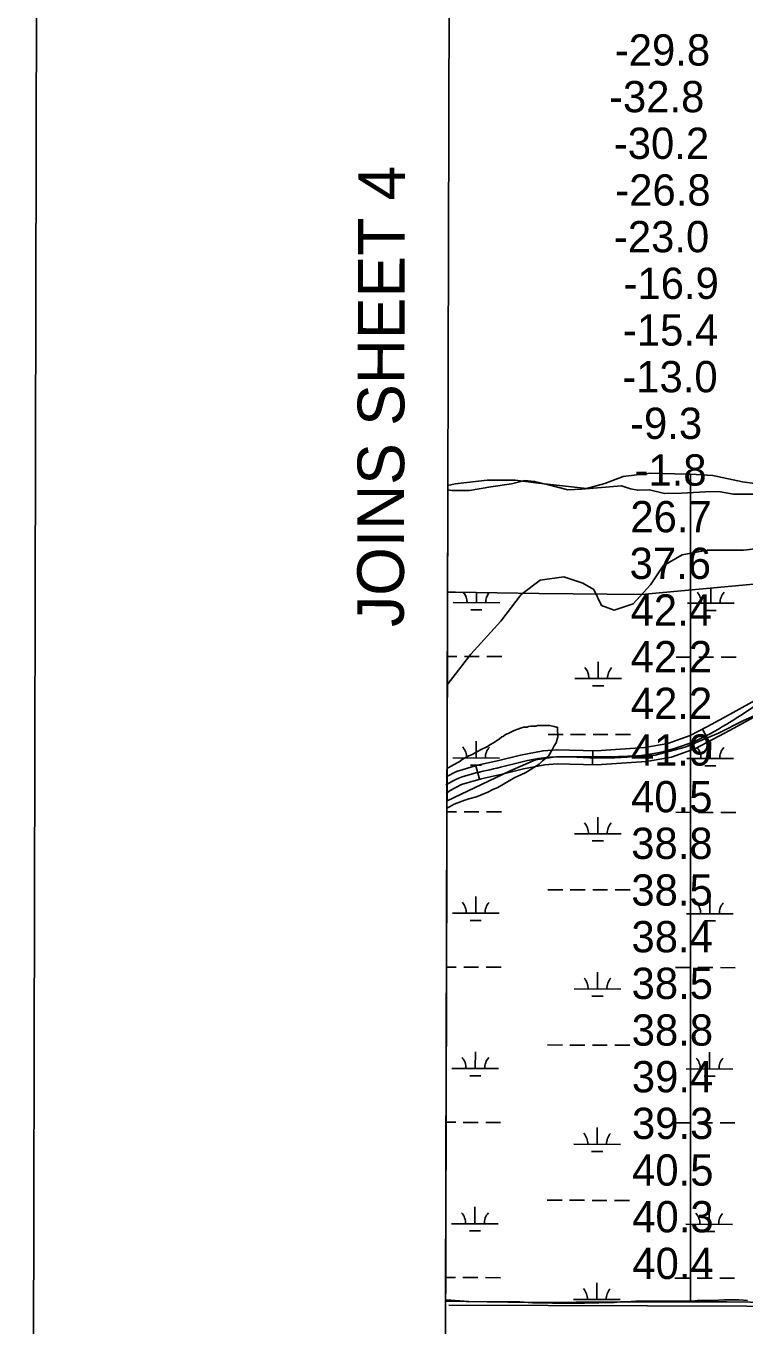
# Model space of a CAD drawing. Extents: x 3180038 to 3217926, y 922069 to 947485.
# Drawn here: x 3183373 to 3184913, y 930412 to 933197 of the extents above; entities that cross this region are included whole.
import ezdxf

# ---------------------------------------------------------------- set-up
doc = ezdxf.new("R2010")
doc.units = 0
for name, color, linetype in [('V-ANNO-SYMB', 7, 'Continuous'), ('V-ANNO-TEXT', 7, 'Continuous'), ('V-GRID-FRAM', 7, 'Continuous'), ('V-RIVR-EDGE', 7, 'Continuous'), ('V-RIVR-RANG', 7, 'Continuous'), ('V-ROAD-CNTR', 7, 'Continuous'), ('V-SITE-VEGE', 7, 'Continuous'), ('V-TOPO-SHOR', 7, 'Continuous'), ('V-WETL-SWMP', 7, 'Continuous')]:
    doc.layers.add(name, color=color, linetype=linetype)

msp = doc.modelspace()

# ---------------------------------------------------------------- linework, layer by layer
at = {"layer": 'V-ANNO-SYMB'}
msp.add_lwpolyline([(3183372.7, 923354.1), (3216455.8, 923279.5), (3216507.5, 946196), (3183424.3, 946270.6), (3183372.7, 923354.1)], dxfattribs=at)
at = {"layer": 'V-GRID-FRAM'}
msp.add_lwpolyline([(3184312.7, 945707.9), (3215616.6, 945637.4), (3215583.5, 927448.1), (3184263.7, 927518.7), (3184312.7, 945707.9)], dxfattribs=at)
at = {"layer": 'V-RIVR-EDGE'}
msp.add_lwpolyline([(3184276.3, 932203.3), (3184285.1, 932201.9), (3184322.5, 932202.1), (3184368.2, 932209.6), (3184412.4, 932216.2), (3184441.6, 932223.2), (3184462, 932221.6), (3184492.2, 932213.9), (3184533.6, 932203.7), (3184562.5, 932205.2), (3184605.8, 932208.7), (3184648.4, 932211.7), (3184667.3, 932205.6), (3184683.1, 932202.5), (3184708.4, 932203.6), (3184740.3, 932195.3), (3184777.2, 932196.4), (3184828.1, 932199.4), (3184856.1, 932199.9), (3184888.4, 932194), (3184938.6, 932194.2)], dxfattribs=at)
at = {"layer": 'V-ROAD-CNTR'}
for p, q in [((3184822, 931690.9), (3184835.8, 931664.2)), ((3184586.9, 931644.2), (3184586.2, 931614.2)), ((3184336, 931612), (3184344.4, 931583.2))]:
    msp.add_line(p, q, dxfattribs=at)
for points in [[(3184272.6, 931588.5), (3184294.6, 931599.9), (3184340.2, 931613.3), (3184385.4, 931623.5), (3184432.2, 931635.1), (3184480.5, 931644.2), (3184509.9, 931646), (3184593.9, 931644.1), (3184698, 931651.1), (3184747.7, 931659.9), (3184795.1, 931676.9), (3184830.8, 931695.4), (3184866.8, 931714.7), (3184961.2, 931766.7)], [(3184272.5, 931553), (3184281.1, 931559.2), (3184305.8, 931571.9), (3184347.7, 931584.2), (3184392.4, 931594.3), (3184438.6, 931605.8), (3184484.2, 931614.4), (3184510.5, 931616), (3184594.6, 931614), (3184701.6, 931621.3), (3184755.4, 931630.8), (3184807.1, 931649.4), (3184844.8, 931668.9), (3184881.1, 931688.3), (3184974.8, 931740)]]:
    msp.add_lwpolyline(points, dxfattribs=at)
msp.add_spline([(3184272.5, 931571.5), (3184273.3, 931572), (3184388.9, 931608.9), (3184482.3, 931629.3), (3184594.3, 931629), (3184801.1, 931663.1), (3184874, 931701.5), (3185066.2, 931799.5), (3185255.8, 931784.9), (3185463.4, 931779.9), (3185599.9, 931763.6), (3185790.3, 931711.5), (3185913, 931645.5), (3186095, 931571.4), (3186297.6, 931563.8), (3186567.5, 931553), (3186727.4, 931556.9), (3186879, 931529.3), (3186914.3, 931400.2), (3186887.7, 931205.9), (3186857.5, 930948.7), (3186884.4, 930867.9), (3186934.5, 930827.1), (3186969.1, 930750.7), (3186952, 930670.5)], degree=3, dxfattribs=at)
at = {"layer": 'V-SITE-VEGE'}
for p, q in [((3184291.7, 932216.1), (3184276.3, 932213)), ((3184360.3, 932223.9), (3184291.7, 932216.1)), ((3184420.8, 932224.4), (3184360.3, 932223.9)), ((3184470.3, 932217.7), (3184420.8, 932224.4)), ((3184573.1, 932206.2), (3184470.3, 932217.7)), ((3184612.9, 932217.3), (3184573.1, 932206.2)), ((3184651.8, 932231.9), (3184612.9, 932217.3)), ((3184710.3, 932239.1), (3184651.8, 932231.9)), ((3184789.3, 932237.1), (3184710.3, 932239.1)), ((3184796.1, 932236.7), (3184789.3, 932237.1)), ((3184844.3, 932234.3), (3184796.1, 932236.7)), ((3184796.1, 932236.7), (3184796.1, 930464.8)), ((3184796.1, 930464.8), (3184796.1, 932236.7)), ((3184907.8, 932220.9), (3184844.3, 932234.3)), ((3184988.1, 932209.2), (3184907.8, 932220.9)), ((3184276.3, 932213), (3184274.7, 931606.3)), ((3184405.4, 931681.1), (3184418.2, 931687.5)), ((3184418.2, 931687.5), (3184426.2, 931690.7)), ((3184426.2, 931690.7), (3184431.8, 931693.1)), ((3184431.8, 931693.1), (3184438.2, 931694.7)), ((3184438.2, 931694.7), (3184446.2, 931694.7)), ((3184446.2, 931694.7), (3184449.4, 931696.3)), ((3184449.4, 931696.3), (3184454.2, 931697.1)), ((3184454.2, 931697.1), (3184464.7, 931697.1)), ((3184464.7, 931697.1), (3184468.7, 931698.7)), ((3184468.7, 931698.7), (3184495.1, 931698.8)), ((3184495.1, 931698.8), (3184503.9, 931696.4)), ((3184503.9, 931696.4), (3184508.7, 931694.8)), ((3184508.7, 931694.8), (3184511.1, 931694.8)), ((3184511.1, 931694.8), (3184511.1, 931686)), ((3184511.1, 931686), (3184511.9, 931679.6)), ((3184359.8, 931653), (3184367.8, 931657.8)), ((3184367.8, 931657.8), (3184377.4, 931663.4)), ((3184377.4, 931663.4), (3184381.4, 931666.6)), ((3184381.4, 931666.6), (3184386.2, 931669.1)), ((3184386.2, 931669.1), (3184391.8, 931673.9)), ((3184391.8, 931673.9), (3184395, 931674.7)), ((3184395, 931674.7), (3184399.8, 931679.5)), ((3184399.8, 931679.5), (3184405.4, 931681.1)), ((3184508.7, 931661.1), (3184503.9, 931654.7)), ((3184511.9, 931673.9), (3184508.7, 931661.1)), ((3184511.9, 931679.6), (3184511.9, 931673.9)), ((3184306.9, 931625.7), (3184319.7, 931633)), ((3184319.7, 931633), (3184328.5, 931636.2)), ((3184328.5, 931636.2), (3184339.7, 931642.6)), ((3184339.7, 931642.6), (3184347.8, 931647.4)), ((3184347.8, 931647.4), (3184359.8, 931653)), ((3184491.9, 931633.1), (3184485.5, 931627.5)), ((3184500.7, 931647.5), (3184491.9, 931633.1)), ((3184503.9, 931654.7), (3184500.7, 931647.5)), ((3184274.7, 931606.3), (3184277.3, 931608.1)), ((3184277.3, 931608.1), (3184288.5, 931614.5)), ((3184288.5, 931614.5), (3184300.5, 931620.9)), ((3184300.5, 931620.9), (3184306.9, 931625.7)), ((3184452.7, 931603.4), (3184443.1, 931597.8)), ((3184466.3, 931612.2), (3184452.7, 931603.4)), ((3184471.9, 931615.4), (3184466.3, 931612.2)), ((3184479.1, 931622.7), (3184471.9, 931615.4)), ((3184485.5, 931627.5), (3184479.1, 931622.7)), ((3184419.9, 931587.4), (3184383.1, 931565.7)), ((3184432.7, 931593), (3184419.9, 931587.4)), ((3184443.1, 931597.8), (3184432.7, 931593)), ((3184362.2, 931555.3), (3184337.4, 931545.7)), ((3184372.6, 931561.7), (3184362.2, 931555.3)), ((3184383.1, 931565.7), (3184372.6, 931561.7)), ((3184274.5, 931521.6), (3184271.6, 930467.4)), ((3184279.8, 931524), (3184274.5, 931521.6)), ((3184290.2, 931529.6), (3184279.8, 931524)), ((3184312.6, 931538.4), (3184290.2, 931529.6)), ((3184321.4, 931541.7), (3184312.6, 931538.4)), ((3184337.4, 931545.7), (3184321.4, 931541.7)), ((3184271.6, 930467.4), (3184282.9, 930466.8)), ((3184282.9, 930466.8), (3184321.4, 930464.4)), ((3184321.4, 930464.4), (3184372.6, 930463.6)), ((3184372.6, 930463.6), (3184430.3, 930463.7)), ((3184430.3, 930463.7), (3184457.5, 930461.3)), ((3184457.5, 930461.3), (3184475.9, 930461.3)), ((3184475.9, 930461.3), (3184500.8, 930460.5)), ((3184500.8, 930460.5), (3184568.9, 930460.6)), ((3184568.9, 930460.6), (3184580.9, 930461.4)), ((3184580.9, 930461.4), (3184600.1, 930461.4)), ((3184600.1, 930461.4), (3184612.9, 930462.2)), ((3184612.9, 930462.2), (3184632.9, 930462.2)), ((3184632.9, 930462.2), (3184646.5, 930463.8)), ((3184646.5, 930463.8), (3184659.4, 930463.9)), ((3184659.4, 930463.9), (3184679.4, 930464.7)), ((3184679.4, 930464.7), (3184796.1, 930464.8)), ((3184796.1, 930464.8), (3184801.1, 930464.8)), ((3184801.1, 930464.8), (3184810.7, 930466.4)), ((3184810.7, 930466.4), (3184843.6, 930466.4)), ((3184843.6, 930466.4), (3184868.4, 930468)), ((3184868.4, 930468), (3184900.4, 930468)), ((3184900.4, 930468), (3184918.1, 930466.4))]:
    msp.add_line(p, q, dxfattribs=at)
at = {"layer": 'V-TOPO-SHOR'}
for points in [[(3184274.6, 931785.9), (3184325.4, 931851.2), (3184389.6, 931922.1), (3184433.5, 931979.5), (3184474.1, 932009.9), (3184524.7, 932016.7), (3184565.3, 932003.2), (3184588.9, 931989.7), (3184605.8, 931955.9), (3184632.8, 931945.8), (3184673.4, 931959.3), (3184710.5, 931999.8), (3184737.6, 932040.3), (3184778.1, 932064), (3184832.1, 932074.1), (3184909.8, 932074.1), (3184997.7, 932084.3)], [(3184273.4, 931536.5), (3184409.9, 931601.2), (3184463.9, 931624.9), (3184507.9, 931631.6), (3184551.8, 931631.6), (3184622.7, 931631.6), (3184720.7, 931635), (3184784.9, 931651.9), (3184855.8, 931682.3), (3184909.8, 931709.3), (3184957.1, 931729.6)], [(3184278.2, 930456.1), (3185342.2, 930452.7), (3185592.2, 930452.7), (3186190.1, 930439.2), (3186217.1, 930459.5), (3186240.7, 930496.6), (3186277.9, 930533.8), (3186335.3, 930567.6), (3186382.6, 930601.3), (3186440, 930648.6), (3186477.2, 930672.3)]]:
    msp.add_lwpolyline(points, dxfattribs=at)
at = {"layer": 'V-WETL-SWMP'}
for p, q in [((3184691, 931979.1), (3184961.8, 932004)), ((3184839.4, 931960.4), (3184839.4, 931992.7)), ((3184271.6, 930465.2), (3184275.7, 931983.9)), ((3184275.7, 931983.9), (3184293.1, 931983.9)), ((3184293.1, 931983.9), (3184471, 931981.1)), ((3184337.5, 931961.5), (3184337.5, 931983.2)), ((3184471, 931981.1), (3184691, 931979.1)), ((3184287.5, 931961.7), (3184387.5, 931961.4)), ((3184325.4, 931946.1), (3184349.4, 931946.1)), ((3184789.4, 931960.5), (3184889.4, 931960.3)), ((3184827.3, 931945), (3184851.3, 931945)), ((3184275.4, 931846.2), (3184295.8, 931846.2)), ((3184311.8, 931846.2), (3184343.8, 931846.1)), ((3184359.8, 931846.1), (3184391.8, 931846)), ((3184598.5, 931799.1), (3184598.6, 931835.1)), ((3184765.7, 931845.1), (3184797.7, 931845.1)), ((3184813.7, 931845), (3184845.7, 931845)), ((3184861.7, 931844.9), (3184893.7, 931844.9)), ((3184548.5, 931799.2), (3184648.5, 931799)), ((3184586.5, 931783.7), (3184610.5, 931783.6)), ((3184336.7, 931628.9), (3184336.8, 931664.9)), ((3184491.4, 931679.3), (3184523.4, 931679.2)), ((3184539.4, 931679.2), (3184571.4, 931679.1)), ((3184587.4, 931679), (3184619.4, 931679)), ((3184635.4, 931678.9), (3184667.4, 931678.9)), ((3184838.6, 931627.7), (3184838.7, 931663.7)), ((3184286.7, 931629), (3184386.7, 931628.8)), ((3184324.7, 931613.5), (3184348.7, 931613.4)), ((3184788.6, 931627.8), (3184888.6, 931627.6)), ((3184826.6, 931612.3), (3184850.6, 931612.3)), ((3184274.5, 931513.6), (3184295, 931513.5)), ((3184311, 931513.5), (3184343, 931513.4)), ((3184359, 931513.4), (3184391, 931513.3)), ((3184597.8, 931466.4), (3184597.9, 931502.4)), ((3184765, 931512.5), (3184797, 931512.4)), ((3184813, 931512.4), (3184845, 931512.3)), ((3184861, 931512.3), (3184893, 931512.2)), ((3184547.8, 931466.5), (3184647.8, 931466.3)), ((3184585.7, 931451), (3184609.7, 931451)), ((3184336, 931296.2), (3184336, 931332.2)), ((3184490.7, 931346.6), (3184522.7, 931346.5)), ((3184538.7, 931346.5), (3184570.7, 931346.4)), ((3184586.7, 931346.4), (3184618.7, 931346.3)), ((3184634.7, 931346.3), (3184666.7, 931346.2)), ((3184837.9, 931295.1), (3184837.9, 931331.1)), ((3184286, 931296.3), (3184386, 931296.1)), ((3184323.9, 931280.8), (3184347.9, 931280.7)), ((3184787.9, 931295.2), (3184887.9, 931294.9)), ((3184825.8, 931279.7), (3184849.8, 931279.6)), ((3184273.6, 931180.9), (3184294.3, 931180.9)), ((3184310.3, 931180.8), (3184342.3, 931180.7)), ((3184358.3, 931180.7), (3184390.3, 931180.6)), ((3184597, 931133.7), (3184597.1, 931169.7)), ((3184764.2, 931179.8), (3184796.2, 931179.7)), ((3184812.2, 931179.7), (3184844.2, 931179.6)), ((3184860.2, 931179.6), (3184892.2, 931179.5)), ((3184547, 931133.9), (3184647, 931133.6)), ((3184585, 931118.3), (3184609, 931118.3)), ((3184335.2, 930963.5), (3184335.3, 930999.5)), ((3184489.9, 931013.9), (3184521.9, 931013.8)), ((3184537.9, 931013.8), (3184569.9, 931013.7)), ((3184585.9, 931013.7), (3184617.9, 931013.6)), ((3184633.9, 931013.6), (3184665.9, 931013.5)), ((3184837.1, 930962.4), (3184837.2, 930998.4)), ((3184285.2, 930963.6), (3184385.2, 930963.4)), ((3184787.1, 930962.5), (3184887.1, 930962.3)), ((3184323.2, 930948.1), (3184347.2, 930948.1)), ((3184825.1, 930947), (3184849.1, 930946.9)), ((3184272.7, 930848.2), (3184293.5, 930848.2)), ((3184309.5, 930848.1), (3184341.5, 930848.1)), ((3184357.5, 930848), (3184389.5, 930848)), ((3184596.3, 930801.1), (3184596.4, 930837.1)), ((3184763.5, 930847.1), (3184795.5, 930847)), ((3184811.5, 930847), (3184843.5, 930846.9)), ((3184859.5, 930846.9), (3184891.4, 930846.8)), ((3184546.3, 930801.2), (3184646.3, 930801)), ((3184584.2, 930785.7), (3184608.2, 930785.6)), ((3184334.5, 930630.8), (3184334.5, 930666.8)), ((3184489.2, 930681.2), (3184521.2, 930681.2)), ((3184537.2, 930681.1), (3184569.2, 930681.1)), ((3184585.2, 930681), (3184617.2, 930681)), ((3184633.2, 930680.9), (3184665.2, 930680.8)), ((3184836.4, 930629.7), (3184836.4, 930665.7)), ((3184284.5, 930631), (3184384.5, 930630.7)), ((3184786.4, 930629.8), (3184886.4, 930629.6)), ((3184322.4, 930615.4), (3184346.4, 930615.4)), ((3184824.3, 930614.3), (3184848.3, 930614.3)), ((3184271.8, 930515.6), (3184292.8, 930515.5)), ((3184308.8, 930515.5), (3184340.8, 930515.4)), ((3184356.8, 930515.4), (3184388.8, 930515.3)), ((3184595.5, 930468.4), (3184595.6, 930504.4)), ((3184762.7, 930514.4), (3184794.7, 930514.4)), ((3184810.7, 930514.3), (3184842.7, 930514.3)), ((3184858.7, 930514.2), (3184890.7, 930514.2)), ((3184449.3, 930462.5), (3184271.6, 930465.2)), ((3184653.1, 930463.6), (3184449.3, 930462.5)), ((3184545.5, 930468.5), (3184645.5, 930468.3)), ((3184873.1, 930463.5), (3184653.1, 930463.6)), ((3185096.3, 930461), (3184873.1, 930463.5))]:
    msp.add_line(p, q, dxfattribs=at)
for centre, start, end in [((3184282.2, 931962.1), 359.099, 37.5569), ((3184392.7, 931961.9), 143.6561, 180.6427), ((3184784.1, 931961), 359.099, 40.6427), ((3184894.6, 931960.8), 139.099, 180.6427), ((3184543.3, 931799.7), 359.099, 40.6427), ((3184653.8, 931799.4), 139.099, 180.6427), ((3184281.5, 931629.5), 359.099, 40.6427), ((3184392, 931629.2), 139.099, 180.6427), ((3184783.4, 931628.3), 359.099, 40.6427), ((3184893.9, 931628.1), 139.099, 180.6427), ((3184542.5, 931467), 359.099, 40.6427), ((3184653, 931466.8), 139.099, 180.6427), ((3184280.7, 931296.8), 359.099, 40.6427), ((3184391.2, 931296.5), 139.099, 180.6427), ((3184782.6, 931295.7), 359.099, 40.6427), ((3184893.1, 931295.4), 139.099, 180.6427), ((3184541.8, 931134.3), 359.099, 40.6427), ((3184652.3, 931134.1), 139.099, 180.6427), ((3184280, 930964.1), 359.099, 40.6427), ((3184390.5, 930963.9), 139.099, 180.6427), ((3184781.9, 930963), 359.099, 40.6427), ((3184892.4, 930962.7), 139.099, 180.6427), ((3184541, 930801.7), 359.099, 40.6427), ((3184651.5, 930801.4), 139.099, 180.6427), ((3184279.2, 930631.4), 359.099, 40.6427), ((3184389.7, 930631.2), 139.099, 180.6427), ((3184781.1, 930630.3), 359.099, 40.6427), ((3184891.6, 930630.1), 139.099, 180.6427), ((3184540.3, 930469), 359.099, 40.6427), ((3184650.8, 930468.7), 139.099, 180.6427)]:
    msp.add_arc(centre, 35.2, start, end, dxfattribs=at)

# ---------------------------------------------------------------- texts
at = {"layer": 'V-ANNO-TEXT'}
msp.add_text('JOINS SHEET 4', height=100, rotation=89.8708, dxfattribs=at).set_placement((3184182.1, 931909.5))
at = {"layer": 'V-RIVR-RANG'}
for s, p in [('-29.8', (3184634, 933112.5)), ('-32.8', (3184621.6, 933012.5)), ('-30.2', (3184631.9, 932912.5)), ('-26.8', (3184635, 932812.5)), ('-23.0', (3184632.1, 932712.5)), ('-16.9', (3184652.7, 932612.5)), ('-15.4', (3184651.4, 932512.5)), ('-13.0', (3184650.1, 932412.5)), ('-9.3', (3184666.7, 932312.5)), ('-1.8', (3184676.2, 932212.5))]:
    msp.add_text(s, height=67, dxfattribs=at).set_placement(p)
for s, p in [('26.7', (3184667.3, 932112.5)), ('37.6', (3184665.7, 932012.5)), ('42.4', (3184667.8, 931912.5)), ('42.2', (3184668.1, 931812.5)), ('42.2', (3184668.3, 931712.5)), ('41.9', (3184668.3, 931612.5)), ('40.5', (3184668.9, 931512.5)), ('38.8', (3184669.1, 931412.5)), ('38.5', (3184669.4, 931312.5)), ('38.4', (3184669.7, 931212.5)), ('38.5', (3184669.9, 931112.5)), ('38.8', (3184670.2, 931012.5)), ('39.4', (3184670.5, 930912.5)), ('39.3', (3184670.7, 930812.5)), ('40.5', (3184671, 930712.5)), ('40.3', (3184671.3, 930612.5)), ('40.4', (3184671.5, 930512.5))]:
    msp.add_text(s, height=67, rotation=0.0083, dxfattribs=at).set_placement(p)

doc.saveas('drawing.dxf')
